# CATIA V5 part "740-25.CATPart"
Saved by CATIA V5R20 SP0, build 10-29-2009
Part number: 740-25
Bounding box of the stored display mesh (mm): x -23.9 to 23.9, y -22 to 23.845, z -23 to 12
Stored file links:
  C:\Users\Utente\Desktop\IO LAVORO\3D X SITO CF\X SITO\740\740-25.CATPart
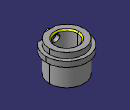
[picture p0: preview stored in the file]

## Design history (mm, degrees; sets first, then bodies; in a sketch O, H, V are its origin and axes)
Set1
  DatumSurface1 to DatumSurface35 "740-25"
Body1 (main body)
